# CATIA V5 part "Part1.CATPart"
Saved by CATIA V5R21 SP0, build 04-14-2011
Part number: Part1
Bounding box of the stored display mesh (mm): x -87.99 to 150, y -137.404 to 137.404, z -15.95 to 15.95
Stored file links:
  C:\Users\H4NNiB4L\Desktop\CATIA How to Designa Y-Shaped Pipe Fiting\Part1.CATPart
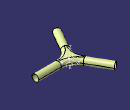
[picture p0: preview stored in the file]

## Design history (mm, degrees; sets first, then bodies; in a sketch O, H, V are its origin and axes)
AxisSystem1: origin (0, 0, 0), X (1, 0, 0), Y (0, 1, 0), Z (0, 0, 1)
Body1 (main body)
  Plane1: type Offset, RefPlane YZ plane of AxisSystem1, Offset 50
  Plane2: type Angle, RefPlane YZ plane of AxisSystem1, Direction edge [ZX plane of AxisSystem1 | YZ plane of AxisSystem1], Angle 60
  Plane3: type Offset, RefPlane Plane2, Offset 50, reversed
  Plane4: type Angle, RefPlane YZ plane of AxisSystem1, Direction edge [ZX plane of AxisSystem1 | YZ plane of AxisSystem1], Angle 120
  Plane5: type Offset, RefPlane Plane4, Offset 50
  Sketch1 on Plane1, origin (50, 0, 0), H (0, 1, 0), V (0, 0, 1)
    circle A1 centre (0, 0) radius 15
    radius A1 = 15
  Sketch2 on Plane5, origin (-25, 43.3013, 0), H (-0.866, -0.5, 0), V (0, 0, 1)
    circle A1 centre (0, 0) radius 15
    radius A1 = 15
  Sketch3 on Plane3, origin (-25, -43.3013, 0), H (-0.866, 0.5, 0), V (0, 0, 1)
    circle A1 centre (0, 0) radius 15
    radius A1 = 15
  Extrude1: Lim1 100, Lim2 0, Element1 Sketch3
  Extrude2: Lim1 100, Lim2 0, Element1 Sketch2
  Extrude3: Lim1 100, Lim2 0, Element1 Sketch1
  Split1: ToCut Extrude3, Cutting XY plane of AxisSystem1
  Split2: ToCut Extrude1, Cutting XY plane of AxisSystem1
  Split3: ToCut Extrude2, Cutting XY plane of AxisSystem1
  Loft1: Sections (edge of Extrude3; edge of Extrude1)
  Loft2: Sections (edge of Extrude3; edge of Extrude2)
  Loft3: Sections (edge of Loft2; edge of Loft1)
  StIsoparamCurveFeature1 "CATStIsoparamCurveFeatureName": Support Loft2, Direction {line type PtDir, RefPoint {point type OnSurface, Support Loft2, Length 11.608, Direction (0.9558, -0.2942, 0)}, Direction (-905.4866, 371.9092, 0), LENGTH 0, LENGTH 10}, Children {point type OnSurface, Support Loft2, Length 11.608, Direction (0.9558, -0.2942, 0)}, BRep face of Loft2
  StIsoparamCurveFeature2 "CATStIsoparamCurveFeatureName": Support Loft1, Direction {line type PtDir, RefPoint {point type OnSurface, Support Loft1, Length 14.2222, Direction (0.9643, 0.2647, 0)}, Direction (-909.5752, -341.6748, 0), LENGTH 0, LENGTH 10}, Children {point type OnSurface, Support Loft1, Length 14.2222, Direction (0.9643, 0.2647, 0)}, BRep face of Loft1
  StIsoparamCurveFeature3 "CATStIsoparamCurveFeatureName": Support Loft3, Direction {line type PtDir, RefPoint {point type OnSurface, Support Loft3, Length 5.3292, Direction (-0.7815, -0.624, 0)}, Direction (-38.4074, -952.4936, -0.0002), LENGTH 0, LENGTH 10}, Children {point type OnSurface, Support Loft3, Length 5.3292, Direction (-0.7815, -0.624, 0)}, BRep face of Loft3
  Split4: ToCut Loft2, Cutting StIsoparamCurveFeature1
  Split5: ToCut Loft1, Cutting StIsoparamCurveFeature2
  Split6: ToCut Loft3, Cutting StIsoparamCurveFeature3
  Fill1: Boundary (edge of Extrude2; StIsoparamCurveFeature3; edge of Extrude1; StIsoparamCurveFeature2; edge of Extrude3; StIsoparamCurveFeature1)
  MultiSel1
